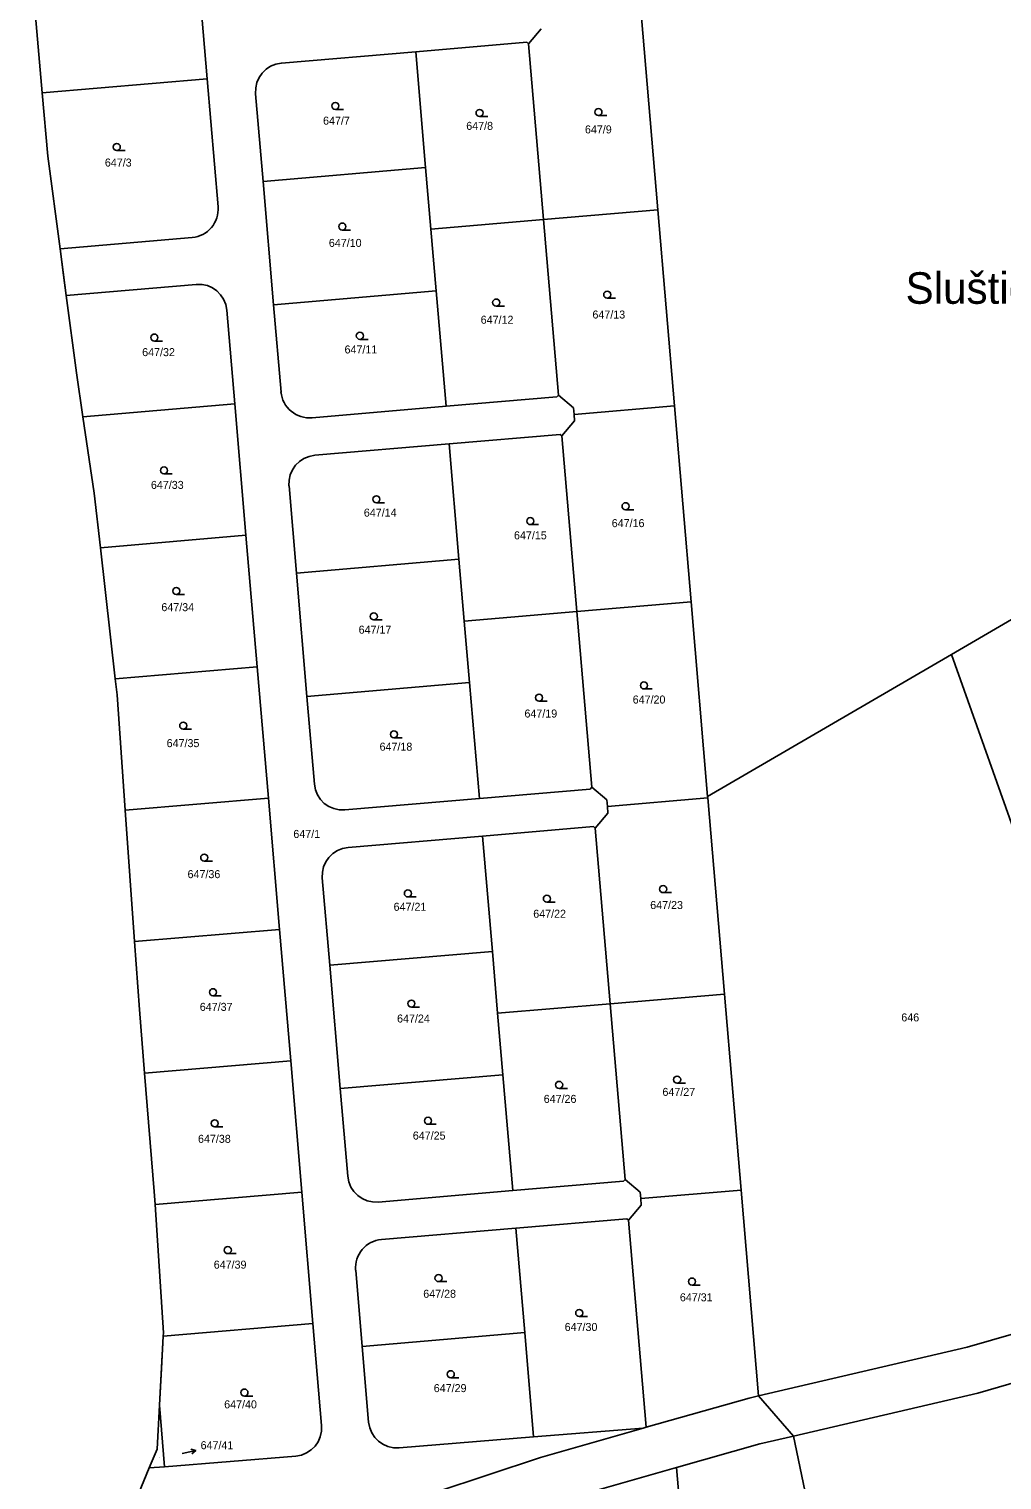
# Model space of a CAD drawing. Extents: x -725765 to -723182, y -1052705 to -1049154.
# Drawn here: x -725541.7 to -725335, y -1050690.2 to -1050382 of the extents above; entities that cross this region are included whole.
import ezdxf

# ---------------------------------------------------------------- set-up
doc = ezdxf.new("R2010")
doc.units = 0
for name, color, linetype in [('Vrstva 1', 7, 'Continuous'), ('Vrstva 13', 7, 'Continuous'), ('Vrstva 15', 7, 'Continuous'), ('Vrstva 16', 7, 'Continuous'), ('Vrstva 18', 7, 'Continuous'), ('Vrstva 25', 7, 'Continuous'), ('Vrstva 52', 7, 'Continuous')]:
    doc.layers.add(name, color=color, linetype=linetype)

msp = doc.modelspace()

# ---------------------------------------------------------------- linework, layer by layer
at = {"layer": 'Vrstva 1'}
for points in [[(-725507.02, -1050355.02), (-725503.83, -1050392.56)], [(-725408.13, -1050420.35), (-725411.67, -1050378.7)], [(-725435.57, -1050385.1), (-725432.88, -1050381.91)], [(-725459.51, -1050386.79), (-725435.95, -1050384.78)], [(-725435.95, -1050384.78), (-725435.57, -1050385.1)], [(-725435.57, -1050385.1), (-725432.4, -1050422.41)], [(-725488.06, -1050389.21), (-725459.51, -1050386.79)], [(-725457.42, -1050411.4), (-725459.51, -1050386.79)], [(-725503.83, -1050392.56), (-725538.86, -1050395.54)], [(-725503.83, -1050392.56), (-725501.52, -1050419.76)], [(-725491.94, -1050414.33), (-725493.53, -1050395.7)], [(-725457.42, -1050411.4), (-725491.94, -1050414.33)], [(-725456.31, -1050424.45), (-725457.42, -1050411.4)], [(-725489.71, -1050440.53), (-725491.94, -1050414.33)], [(-725432.4, -1050422.41), (-725456.31, -1050424.45)], [(-725408.13, -1050420.35), (-725432.4, -1050422.41)], [(-725432.4, -1050422.41), (-725429.22, -1050459.72)], [(-725404.59, -1050462), (-725408.13, -1050420.35)], [(-725456.31, -1050424.45), (-725455.19, -1050437.6)], [(-725506.99, -1050426.25), (-725535.08, -1050428.63)], [(-725533.77, -1050438.56), (-725506.14, -1050436.21)], [(-725489.71, -1050440.53), (-725455.19, -1050437.6)], [(-725453.1, -1050462.11), (-725455.19, -1050437.6)], [(-725488.14, -1050459.07), (-725489.71, -1050440.53)], [(-725216.41, -1050439.34), (-725345.73, -1050514.8)], [(-725499.65, -1050441.68), (-725497.96, -1050461.61)], [(-725530.21, -1050464.35), (-725497.96, -1050461.61)], [(-725497.96, -1050461.61), (-725495.58, -1050489.51)], [(-725453.1, -1050462.11), (-725481.56, -1050464.53)], [(-725429.55, -1050460.11), (-725453.1, -1050462.11)], [(-725429.22, -1050459.72), (-725429.55, -1050460.11)], [(-725426.03, -1050462.42), (-725429.22, -1050459.72)], [(-725425.91, -1050463.81), (-725426.03, -1050462.42)], [(-725425.91, -1050463.81), (-725404.59, -1050462)], [(-725401.05, -1050503.65), (-725404.59, -1050462)], [(-725428.49, -1050468.4), (-725425.79, -1050465.21)], [(-725425.79, -1050465.21), (-725425.91, -1050463.81)], [(-725452.43, -1050470.08), (-725428.87, -1050468.08)], [(-725428.87, -1050468.08), (-725428.49, -1050468.4)], [(-725425.31, -1050505.71), (-725428.49, -1050468.4)], [(-725480.97, -1050472.51), (-725452.43, -1050470.08)], [(-725450.34, -1050494.59), (-725452.43, -1050470.08)], [(-725484.87, -1050497.53), (-725486.44, -1050479)], [(-725526.5, -1050492.14), (-725495.58, -1050489.51)], [(-725495.58, -1050489.51), (-725493.21, -1050517.41)], [(-725484.87, -1050497.53), (-725450.34, -1050494.59)], [(-725449.22, -1050507.74), (-725450.34, -1050494.59)], [(-725482.64, -1050523.73), (-725484.87, -1050497.53)], [(-725449.22, -1050507.74), (-725425.31, -1050505.71)], [(-725425.31, -1050505.71), (-725401.05, -1050503.65)], [(-725422.14, -1050543.02), (-725425.31, -1050505.71)], [(-725397.53, -1050545.02), (-725401.05, -1050503.65)], [(-725448.11, -1050520.79), (-725449.22, -1050507.74)], [(-725345.73, -1050514.8), (-725397.53, -1050545.02)], [(-725345.73, -1050514.8), (-725298.36, -1050648.24)], [(-725523.34, -1050519.97), (-725493.21, -1050517.41)], [(-725493.21, -1050517.41), (-725490.83, -1050545.31)], [(-725448.11, -1050520.79), (-725482.64, -1050523.73)], [(-725446.02, -1050545.4), (-725448.11, -1050520.79)], [(-725481.06, -1050542.36), (-725482.64, -1050523.73)], [(-725521.21, -1050547.89), (-725490.83, -1050545.31)], [(-725490.83, -1050545.31), (-725488.46, -1050573.21)], [(-725446.02, -1050545.4), (-725474.57, -1050547.83)], [(-725422.46, -1050543.4), (-725446.02, -1050545.4)], [(-725422.14, -1050543.02), (-725422.46, -1050543.4)], [(-725418.95, -1050545.71), (-725422.14, -1050543.02)], [(-725418.83, -1050547.11), (-725418.95, -1050545.71)], [(-725418.83, -1050547.11), (-725397.51, -1050545.29)], [(-725397.51, -1050545.29), (-725397.53, -1050545.02)], [(-725393.96, -1050586.94), (-725397.51, -1050545.29)], [(-725421.4, -1050551.7), (-725418.71, -1050548.5)], [(-725418.71, -1050548.5), (-725418.83, -1050547.11)], [(-725445.34, -1050553.38), (-725421.79, -1050551.37)], [(-725421.79, -1050551.37), (-725421.4, -1050551.7)], [(-725421.4, -1050551.7), (-725418.23, -1050589)], [(-725473.89, -1050555.8), (-725445.34, -1050553.38)], [(-725443.26, -1050577.89), (-725445.34, -1050553.38)], [(-725477.79, -1050580.82), (-725479.37, -1050562.29)], [(-725519.23, -1050575.82), (-725488.46, -1050573.21)], [(-725488.46, -1050573.21), (-725486.09, -1050601.11)], [(-725443.26, -1050577.89), (-725477.79, -1050580.82)], [(-725442.14, -1050591.04), (-725443.26, -1050577.89)], [(-725475.56, -1050607.02), (-725477.79, -1050580.82)], [(-725418.23, -1050589), (-725442.14, -1050591.04)], [(-725393.96, -1050586.94), (-725418.23, -1050589)], [(-725418.23, -1050589), (-725415.06, -1050626.31)], [(-725390.42, -1050628.59), (-725393.96, -1050586.94)], [(-725441.03, -1050604.09), (-725442.14, -1050591.04)], [(-725517.12, -1050603.74), (-725486.09, -1050601.11)], [(-725486.09, -1050601.11), (-725483.72, -1050629.01)], [(-725441.03, -1050604.09), (-725475.56, -1050607.02)], [(-725438.94, -1050628.7), (-725441.03, -1050604.09)], [(-725473.97, -1050625.66), (-725475.56, -1050607.02)], [(-725514.9, -1050631.66), (-725483.72, -1050629.01)], [(-725483.72, -1050629.01), (-725481.35, -1050656.91)], [(-725438.94, -1050628.7), (-725467.49, -1050631.13)], [(-725415.38, -1050626.7), (-725438.94, -1050628.7)], [(-725415.06, -1050626.31), (-725415.38, -1050626.7)], [(-725411.87, -1050629.01), (-725415.06, -1050626.31)], [(-725411.75, -1050630.4), (-725411.87, -1050629.01)], [(-725411.75, -1050630.4), (-725390.42, -1050628.59)], [(-725386.7, -1050672.3), (-725390.42, -1050628.59)], [(-725414.32, -1050634.99), (-725411.63, -1050631.8)], [(-725411.63, -1050631.8), (-725411.75, -1050630.4)], [(-725438.26, -1050636.67), (-725414.7, -1050634.67)], [(-725414.7, -1050634.67), (-725414.32, -1050634.99)], [(-725414.32, -1050634.99), (-725410.59, -1050678.98)], [(-725466.81, -1050639.1), (-725438.26, -1050636.67)], [(-725436.38, -1050658.85), (-725438.26, -1050636.67)], [(-725470.9, -1050661.79), (-725472.28, -1050645.58)], [(-725321.26, -1050655.84), (-725342.44, -1050661.95)], [(-725513.15, -1050659.61), (-725481.35, -1050656.91)], [(-725481.35, -1050656.91), (-725479.51, -1050678.62)], [(-725436.38, -1050658.85), (-725470.9, -1050661.79)], [(-725434.49, -1050681.03), (-725436.38, -1050658.85)], [(-725469.54, -1050677.86), (-725470.9, -1050661.79)], [(-725386.7, -1050672.3), (-725342.44, -1050661.95)], [(-725340.16, -1050671.69), (-725318.22, -1050665.34)], [(-725379.29, -1050680.83), (-725340.16, -1050671.69)], [(-725512.89, -1050687.34), (-725513.94, -1050674.26)], [(-725410.59, -1050678.98), (-725388.73, -1050672.77)], [(-725388.73, -1050672.77), (-725386.7, -1050672.3)], [(-725379.29, -1050680.83), (-725386.7, -1050672.3)], [(-725434.49, -1050681.03), (-725463.06, -1050683.33)], [(-725411.22, -1050679.16), (-725434.49, -1050681.03)], [(-725433.05, -1050685.36), (-725411.22, -1050679.16)], [(-725411.22, -1050679.16), (-725410.59, -1050678.98)], [(-725386.45, -1050682.51), (-725379.29, -1050680.83)], [(-725370.88, -1050721.27), (-725379.29, -1050680.83)], [(-725404.14, -1050687.53), (-725386.45, -1050682.51)], [(-725512.89, -1050687.34), (-725516.11, -1050687.6)], [(-725485.01, -1050685.1), (-725512.89, -1050687.34)], [(-725455.24, -1050692.73), (-725433.05, -1050685.36)], [(-725429.9, -1050694.85), (-725404.14, -1050687.53)], [(-725401.06, -1050723.73), (-725404.14, -1050687.53)]]:
    msp.add_lwpolyline(points, dxfattribs=at)
for centre, radius, start, end in [((-725487.54, -1050395.2), 6.02, 95.1783, 184.7501), ((-725507.49, -1050420.28), 5.99, 274.7268, 4.959), ((-725505.63, -1050442.18), 6, 4.9818, 94.9175), ((-725482.13, -1050458.52), 6.04, 185.1186, 275.3899), ((-725480.47, -1050478.49), 6, 94.9722, 184.9182), ((-725475.08, -1050541.86), 6, 184.9642, 274.919), ((-725473.37, -1050561.8), 6.02, 94.7931, 184.7098), ((-725467.98, -1050625.14), 6.01, 185.0097, 274.6661), ((-725466.31, -1050645.07), 6, 94.8207, 184.8429), ((-725463.55, -1050677.34), 6.01, 185.0184, 274.6661), ((-725485.51, -1050679.1), 6.02, 274.8334, 4.6245)]:
    msp.add_arc(centre, radius, start, end, dxfattribs=at)
at = {"layer": 'Vrstva 13'}
for points in [[(-725541.66, -1050363.64), (-725538.86, -1050395.54)], [(-725538.86, -1050395.54), (-725537.69, -1050408.94)], [(-725537.69, -1050408.94), (-725535.08, -1050428.63)], [(-725535.08, -1050428.63), (-725533.77, -1050438.56)], [(-725533.77, -1050438.56), (-725531.59, -1050455)], [(-725530.21, -1050464.35), (-725531.59, -1050455)], [(-725527.82, -1050480.53), (-725530.21, -1050464.35)], [(-725527.82, -1050480.53), (-725526.5, -1050492.14)], [(-725526.5, -1050492.14), (-725523.34, -1050519.97)], [(-725523.34, -1050519.97), (-725522.95, -1050523.36)], [(-725522.95, -1050523.36), (-725521.21, -1050547.89)], [(-725521.21, -1050547.89), (-725519.23, -1050575.82)], [(-725519.23, -1050575.82), (-725518.21, -1050590.25)], [(-725518.21, -1050590.25), (-725517.12, -1050603.74)], [(-725517.12, -1050603.74), (-725515.08, -1050628.88)], [(-725515.08, -1050628.88), (-725514.9, -1050631.66)], [(-725514.9, -1050631.66), (-725513.11, -1050658.92)], [(-725513.94, -1050674.26), (-725513.15, -1050659.61)], [(-725513.15, -1050659.61), (-725513.11, -1050658.92)], [(-725514.45, -1050683.6), (-725513.94, -1050674.26)], [(-725514.45, -1050683.6), (-725516.11, -1050687.6)], [(-725518.39, -1050693.08), (-725516.11, -1050687.6)]]:
    msp.add_lwpolyline(points, dxfattribs=at)
at = {"layer": 'Vrstva 25'}
for points in [[(-725476.6, -1050399.05), (-725474.85, -1050399.05)], [(-725445.97, -1050400.54), (-725444.22, -1050400.54)], [(-725420.72, -1050400.35), (-725418.97, -1050400.35)], [(-725523.02, -1050407.78), (-725521.27, -1050407.78)], [(-725475.12, -1050424.67), (-725473.37, -1050424.67)], [(-725442.44, -1050440.82), (-725440.69, -1050440.82)], [(-725418.86, -1050439.15), (-725417.11, -1050439.15)], [(-725515.03, -1050448.25), (-725513.28, -1050448.25)], [(-725471.4, -1050447.88), (-725469.65, -1050447.88)], [(-725512.99, -1050476.47), (-725511.24, -1050476.47)], [(-725467.88, -1050482.6), (-725466.13, -1050482.6)], [(-725414.96, -1050484.08), (-725413.21, -1050484.08)], [(-725435.2, -1050487.24), (-725433.45, -1050487.24)], [(-725510.39, -1050502.09), (-725508.64, -1050502.09)], [(-725468.43, -1050507.48), (-725466.68, -1050507.48)], [(-725411.06, -1050522.15), (-725409.31, -1050522.15)], [(-725433.34, -1050524.74), (-725431.59, -1050524.74)], [(-725508.91, -1050530.69), (-725507.16, -1050530.69)], [(-725464.16, -1050532.54), (-725462.41, -1050532.54)], [(-725504.45, -1050558.72), (-725502.7, -1050558.72)], [(-725461.19, -1050566.33), (-725459.44, -1050566.33)], [(-725431.67, -1050567.45), (-725429.92, -1050567.45)], [(-725406.98, -1050565.41), (-725405.23, -1050565.41)], [(-725502.6, -1050587.31), (-725500.85, -1050587.31)], [(-725460.45, -1050589.73), (-725458.7, -1050589.73)], [(-725429.07, -1050606.99), (-725427.32, -1050606.99)], [(-725404.01, -1050605.88), (-725402.26, -1050605.88)], [(-725502.22, -1050615.16), (-725500.47, -1050615.16)], [(-725456.92, -1050614.61), (-725455.17, -1050614.61)], [(-725499.44, -1050642.09), (-725497.69, -1050642.09)], [(-725454.69, -1050648.03), (-725452.94, -1050648.03)], [(-725400.85, -1050648.77), (-725399.1, -1050648.77)], [(-725424.8, -1050655.45), (-725423.05, -1050655.45)], [(-725452.09, -1050668.45), (-725450.34, -1050668.45)], [(-725495.91, -1050672.35), (-725494.16, -1050672.35)], [(-725509.17, -1050684.55), (-725506.24, -1050683.92)], [(-725507.32, -1050683.64), (-725506.24, -1050683.92), (-725507.11, -1050684.62)]]:
    msp.add_lwpolyline(points, dxfattribs=at)
for centre in [(-725476.6, -1050398.3), (-725445.97, -1050399.79), (-725420.72, -1050399.6), (-725523.02, -1050407.03), (-725475.12, -1050423.92), (-725418.86, -1050438.4), (-725442.44, -1050440.07), (-725515.03, -1050447.5), (-725471.4, -1050447.13), (-725512.99, -1050475.72), (-725467.88, -1050481.85), (-725414.96, -1050483.33), (-725435.2, -1050486.49), (-725510.39, -1050501.34), (-725468.43, -1050506.73), (-725411.06, -1050521.4), (-725433.34, -1050523.99), (-725508.91, -1050529.94), (-725464.16, -1050531.79), (-725504.45, -1050557.97), (-725406.98, -1050564.66), (-725461.19, -1050565.58), (-725431.67, -1050566.7), (-725502.6, -1050586.56), (-725460.45, -1050588.98), (-725404.01, -1050605.13), (-725429.07, -1050606.24), (-725502.22, -1050614.41), (-725456.92, -1050613.86), (-725499.44, -1050641.34), (-725454.69, -1050647.28), (-725400.85, -1050648.02), (-725424.8, -1050654.7), (-725452.09, -1050667.7), (-725495.91, -1050671.6)]:
    msp.add_circle(centre, 0.75, dxfattribs=at)
at = {"layer": 'Vrstva 52'}
msp.add_lwpolyline([(-725518.39, -1050693.08), (-725516.11, -1050687.6), (-725514.45, -1050683.6), (-725513.94, -1050674.26), (-725513.52, -1050666.46), (-725513.15, -1050659.61), (-725513.11, -1050658.92), (-725514.9, -1050631.66), (-725515.08, -1050628.88), (-725517.12, -1050603.74), (-725518.21, -1050590.25), (-725519.23, -1050575.82), (-725521.21, -1050547.89), (-725522.95, -1050523.36), (-725523.34, -1050519.97), (-725526.5, -1050492.14), (-725527.82, -1050480.53), (-725530.21, -1050464.35), (-725531.59, -1050455), (-725533.77, -1050438.56), (-725534.48, -1050433.19), (-725535.08, -1050428.63), (-725537.69, -1050408.94), (-725538.86, -1050395.54), (-725541.66, -1050363.64)], dxfattribs=at)

# ---------------------------------------------------------------- texts
at = {"layer": 'Vrstva 15'}
msp.add_text('Sluštice', height=6.7, dxfattribs=at).set_placement((-725355.5, -1050440.33))
at = {"layer": 'Vrstva 16'}
msp.add_text('647/41', height=1.7, dxfattribs=at).set_placement((-725505.22, -1050683.63))
at = {"layer": 'Vrstva 18'}
for s, height, p in [('647/7', 1.7, (-725479.21, -1050402.28)), ('647/8', 1.7, (-725448.8, -1050403.39)), ('647/9', 1.7, (-725423.59, -1050404.14)), ('647/3', 1.7, (-725525.55, -1050411.18)), ('647/10', 1.7, (-725477.98, -1050428.25)), ('647/12', 1.7, (-725445.73, -1050444.57)), ('647/13', 1.7, (-725422, -1050443.46)), ('647/32', 1.7, (-725517.63, -1050451.45)), ('647/11', 1.7, (-725474.65, -1050450.88)), ('647/33', 1.7, (-725515.77, -1050479.65)), ('647/14', 1.7, (-725470.55, -1050485.54)), ('647/16', 1.7, (-725417.9, -1050487.77)), ('647/15', 1.7, (-725438.66, -1050490.36)), ('647/34', 1.7, (-725513.55, -1050505.62)), ('647/17', 1.7, (-725471.66, -1050510.4)), ('647/20', 1.7, (-725413.45, -1050525.24)), ('647/19', 1.7, (-725436.44, -1050528.21)), ('647/35', 1.7, (-725512.43, -1050534.5)), ('647/18', 1.7, (-725467.21, -1050535.25)), ('647/1', 1.7, (-725485.52, -1050553.79)), ('647/36', 1.7, (-725507.99, -1050562.33)), ('647/21', 1.7, (-725464.23, -1050569.26)), ('647/23', 1.7, (-725409.73, -1050568.89)), ('647/22', 1.7, (-725434.57, -1050570.74)), ('647/37', 1.7, (-725505.39, -1050590.52)), ('647/24', 1.7, (-725463.49, -1050593)), ('646', 1.7, (-725356.4, -1050592.76)), ('647/27', 1.7, (-725407.13, -1050608.58)), ('647/26', 1.7, (-725432.35, -1050610.07)), ('647/38', 1.7, (-725505.77, -1050618.55)), ('647/25', 1.7, (-725460.15, -1050617.86)), ('647/39', 1.7, (-725502.43, -1050645.27)), ('647/28', 1.7, (-725457.93, -1050651.46)), ('647/31', 1.7, (-725403.43, -1050652.21)), ('647/30', 1.7, (-725427.9, -1050658.51)), ('647/29', 1.7, (-725455.7, -1050671.5)), ('647/40', 1.7, (-725500.21, -1050674.95)), ('647/41', 0.1, (-725514.38, -1050685.47))]:
    msp.add_text(s, height=height, dxfattribs=at).set_placement(p)

doc.saveas('drawing.dxf')
